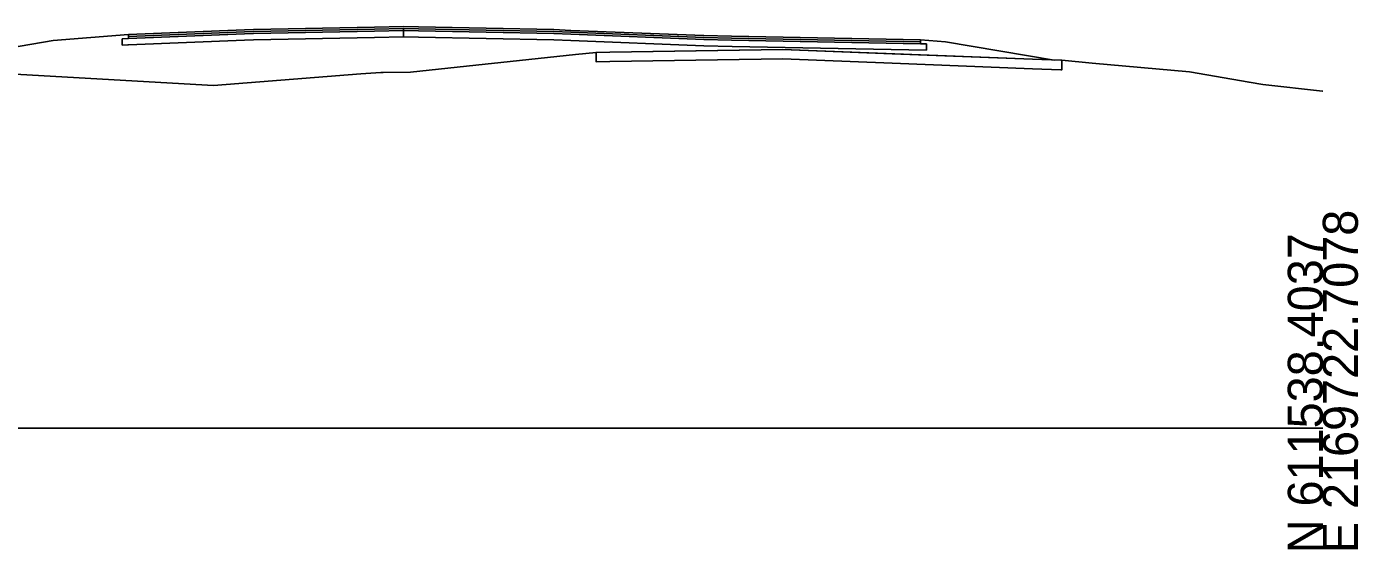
# Model space of a CAD drawing. Extents: x -26 to 1303, y -3010 to 12038.
# Drawn here: x 1196.4 to 1302.8, y 3490.3 to 3532.1 of the extents above; entities that cross this region are included whole.
import ezdxf

# ---------------------------------------------------------------- set-up
doc = ezdxf.new("R2010")
doc.units = 0
for name, color, linetype in [('RD_GPK_XS_Cell', 7, 'Continuous'), ('RD_XS_Base', 7, 'Continuous'), ('RD_XS_ExGround', 7, 'Continuous'), ('RD_XS_ExPaveRet', 7, 'Continuous'), ('RD_XS_Greenside', 7, 'Continuous'), ('RD_XS_Pave', 7, 'Continuous'), ('RD_XS_PaveOvlay_CP', 7, 'Continuous'), ('RD_XS_TieSlope', 7, 'Continuous')]:
    doc.layers.add(name, color=color, linetype=linetype)

msp = doc.modelspace()

# ---------------------------------------------------------------- linework, layer by layer
at = {"layer": 'RD_GPK_XS_Cell'}
msp.add_line((1150, 3500), (1300, 3500), dxfattribs=at)
at = {"layer": 'RD_XS_Base'}
for p, q in [((1214.53, 3531.58), (1224.21, 3531.77)), ((1224.21, 3531.77), (1226.53, 3531.82)), ((1226.53, 3531.96), (1226.53, 3531.98)), ((1226.53, 3531.98), (1226.53, 3531.91)), ((1226.53, 3531.82), (1226.53, 3531.96)), ((1226.53, 3531.91), (1226.53, 3531.32)), ((1226.53, 3531.82), (1226.53, 3531.82)), ((1227.73, 3531.8), (1226.53, 3531.82)), ((1226.53, 3531.82), (1226.53, 3531.82)), ((1226.53, 3531.82), (1226.53, 3531.77)), ((1226.53, 3531.77), (1226.53, 3531.32)), ((1238.53, 3531.58), (1227.73, 3531.8)), ((1204.03, 3531.16), (1204.5, 3531.18)), ((1204.03, 3531.13), (1204.03, 3531.16)), ((1204.03, 3530.66), (1204.03, 3531.13)), ((1204.5, 3530.68), (1204.03, 3530.66)), ((1204.5, 3531.18), (1204.53, 3531.18)), ((1204.53, 3530.68), (1204.5, 3530.68)), ((1204.53, 3531.18), (1213.8, 3531.55)), ((1213.8, 3531.05), (1204.53, 3530.68)), ((1213.8, 3531.55), (1214.53, 3531.58)), ((1214.53, 3531.08), (1213.8, 3531.05)), ((1224.21, 3531.27), (1214.53, 3531.08)), ((1226.53, 3531.32), (1224.21, 3531.27)), ((1226.53, 3531.32), (1227.73, 3531.3)), ((1227.73, 3531.3), (1238.53, 3531.08)), ((1239.89, 3531.53), (1238.53, 3531.58)), ((1238.53, 3531.08), (1239.89, 3531.03)), ((1250.53, 3531.1), (1239.89, 3531.53)), ((1239.89, 3531.03), (1250.53, 3530.6)), ((1252.74, 3531.06), (1250.53, 3531.1)), ((1267.83, 3530.76), (1252.74, 3531.06)), ((1267.9, 3530.75), (1267.83, 3530.76)), ((1268.33, 3530.75), (1267.9, 3530.75)), ((1268.33, 3530.67), (1268.33, 3530.75)), ((1268.33, 3530.25), (1268.33, 3530.67)), ((1250.53, 3530.6), (1252.8, 3530.56)), ((1252.8, 3530.56), (1268.33, 3530.25))]:
    msp.add_line(p, q, dxfattribs=at)
at = {"layer": 'RD_XS_ExGround'}
msp.add_lwpolyline([(1193.12, 3528.46), (1211.34, 3527.43), (1223.11, 3528.35), (1224.71, 3528.47), (1224.89, 3528.47), (1227.07, 3528.5), (1240.28, 3529.91), (1241.91, 3530.08), (1243, 3530.1), (1256.84, 3530.32), (1276.8, 3529.52), (1279.14, 3529.44), (1281.56, 3529.21), (1289.33, 3528.51), (1294.1, 3527.68), (1295.21, 3527.51), (1299.97, 3526.97), (1300, 3526.97)], dxfattribs=at)
at = {"layer": 'RD_XS_ExPaveRet'}
for p, q in [((1279.07, 3529.44), (1276.8, 3529.52)), ((1279.14, 3529.44), (1279.07, 3529.44))]:
    msp.add_line(p, q, dxfattribs=at)
for points in [[(1279.07, 3529.44), (1279.14, 3529.44), (1279.14, 3529.04), (1279.14, 3528.69), (1279.07, 3528.69), (1276.8, 3528.77), (1265.58, 3529.22), (1256.84, 3529.57), (1251.63, 3529.49), (1243, 3529.35), (1241.91, 3529.33), (1241.91, 3529.63), (1241.91, 3530.08), (1243, 3530.1), (1251.63, 3530.24), (1256.84, 3530.32), (1265.58, 3529.97), (1276.8, 3529.52), (1279.07, 3529.44)], [(1256.84, 3530.32), (1251.63, 3530.24), (1243, 3530.1), (1243, 3530.1), (1241.91, 3530.08)], [(1241.91, 3530.08), (1241.91, 3529.63), (1241.91, 3529.33), (1243, 3529.35), (1251.63, 3529.49), (1256.84, 3529.57), (1265.58, 3529.22), (1276.8, 3528.77), (1279.07, 3528.69), (1279.14, 3528.69), (1279.14, 3529.04), (1279.14, 3529.44)], [(1276.8, 3529.52), (1265.58, 3529.97), (1256.84, 3530.32)]]:
    msp.add_lwpolyline(points, dxfattribs=at)
at = {"layer": 'RD_XS_Greenside'}
for p, q in [((1198.53, 3531.02), (1187.22, 3529.13)), ((1269.83, 3530.91), (1278.53, 3529.46))]:
    msp.add_line(p, q, dxfattribs=at)
at = {"layer": 'RD_XS_Pave'}
for p, q in [((1213.8, 3531.87), (1204.53, 3531.5)), ((1213.8, 3531.71), (1204.53, 3531.34)), ((1204.53, 3531.34), (1213.8, 3531.71)), ((1214.53, 3531.9), (1213.8, 3531.87)), ((1214.53, 3531.74), (1213.8, 3531.71)), ((1213.8, 3531.71), (1214.53, 3531.74)), ((1224.21, 3532.09), (1214.53, 3531.9)), ((1224.21, 3531.93), (1214.53, 3531.74)), ((1214.53, 3531.74), (1224.21, 3531.93)), ((1214.53, 3531.58), (1224.21, 3531.77)), ((1226.53, 3532.14), (1224.21, 3532.09)), ((1226.53, 3531.98), (1224.21, 3531.93)), ((1224.21, 3531.93), (1226.53, 3531.98)), ((1224.21, 3531.77), (1226.53, 3531.82)), ((1227.73, 3532.11), (1226.53, 3532.14)), ((1226.53, 3531.96), (1226.53, 3531.98)), ((1226.53, 3531.98), (1227.73, 3531.96)), ((1227.73, 3531.96), (1226.53, 3531.98)), ((1226.53, 3531.98), (1226.53, 3531.98)), ((1226.53, 3531.98), (1226.53, 3531.98)), ((1226.53, 3531.98), (1226.53, 3531.96)), ((1226.53, 3531.82), (1226.53, 3531.96)), ((1226.53, 3531.96), (1226.53, 3531.82)), ((1226.53, 3531.82), (1226.53, 3531.82)), ((1226.53, 3531.82), (1226.53, 3531.82)), ((1226.53, 3531.82), (1227.73, 3531.8)), ((1238.53, 3531.9), (1227.73, 3532.11)), ((1227.73, 3531.96), (1238.53, 3531.74)), ((1238.53, 3531.74), (1227.73, 3531.96)), ((1227.73, 3531.8), (1238.53, 3531.58)), ((1239.89, 3531.84), (1238.53, 3531.9)), ((1238.53, 3531.74), (1239.89, 3531.69)), ((1239.89, 3531.69), (1238.53, 3531.74)), ((1250.53, 3531.42), (1239.89, 3531.84)), ((1239.89, 3531.69), (1250.53, 3531.26)), ((1250.53, 3531.26), (1239.89, 3531.69)), ((1204.53, 3531.18), (1213.8, 3531.55)), ((1204.53, 3531.5), (1204.53, 3531.49)), ((1204.53, 3531.49), (1204.53, 3531.34)), ((1204.53, 3531.34), (1204.53, 3531.33)), ((1204.53, 3531.33), (1204.53, 3531.18)), ((1213.8, 3531.55), (1214.53, 3531.58)), ((1238.53, 3531.58), (1239.89, 3531.53)), ((1239.89, 3531.53), (1250.53, 3531.1)), ((1252.74, 3531.38), (1250.53, 3531.42)), ((1250.53, 3531.26), (1252.74, 3531.22)), ((1252.74, 3531.22), (1250.53, 3531.26)), ((1250.53, 3531.1), (1252.74, 3531.06)), ((1267.83, 3531.07), (1252.74, 3531.38)), ((1252.74, 3531.22), (1267.83, 3530.91)), ((1267.83, 3530.91), (1252.74, 3531.22)), ((1252.74, 3531.06), (1267.83, 3530.76)), ((1267.83, 3531.05), (1267.83, 3531.07)), ((1267.83, 3530.91), (1267.83, 3531.05)), ((1267.83, 3530.89), (1267.83, 3530.91)), ((1267.83, 3530.76), (1267.83, 3530.89))]:
    msp.add_line(p, q, dxfattribs=at)
at = {"layer": 'RD_XS_PaveOvlay_CP'}
for p, q in [((1213.8, 3531.87), (1204.53, 3531.5)), ((1214.53, 3531.9), (1213.8, 3531.87)), ((1224.21, 3532.09), (1214.53, 3531.9)), ((1226.53, 3532.14), (1224.21, 3532.09)), ((1227.73, 3532.11), (1226.53, 3532.14)), ((1238.53, 3531.9), (1227.73, 3532.11)), ((1239.89, 3531.84), (1238.53, 3531.9)), ((1250.53, 3531.42), (1239.89, 3531.84)), ((1252.74, 3531.38), (1250.53, 3531.42)), ((1267.83, 3531.07), (1252.74, 3531.38))]:
    msp.add_line(p, q, dxfattribs=at)
at = {"layer": 'RD_XS_TieSlope'}
for p, q in [((1204.53, 3531.5), (1198.53, 3531.02)), ((1267.83, 3531.07), (1269.83, 3530.91))]:
    msp.add_line(p, q, dxfattribs=at)

# ---------------------------------------------------------------- texts
at = {"layer": 'RD_GPK_XS_Cell'}
for s, p in [('E 2169722.7078', (1302.8, 3490)), ('N 611538.4037', (1300, 3490))]:
    msp.add_text(s, height=2.8, rotation=90, dxfattribs=at).set_placement(p)

doc.saveas('drawing.dxf')
